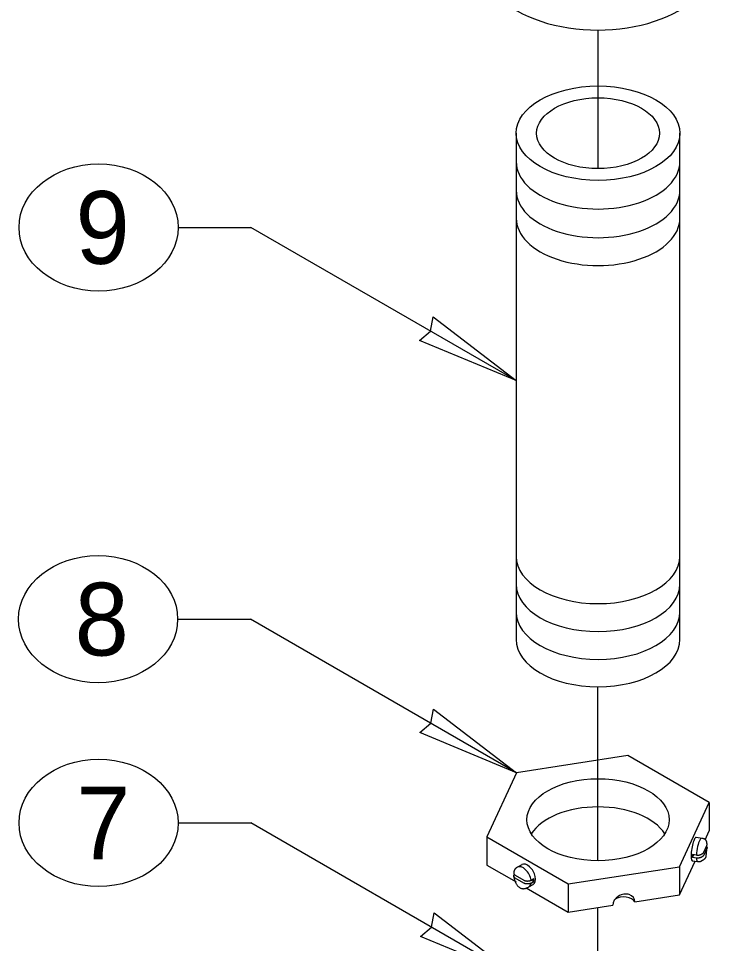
# Model space of a CAD drawing. Extents: x 99862 to 104211, y 98939 to 105076.
# Drawn here: x 100870.4 to 101022.8, y 101634.5 to 101838 of the extents above; entities that cross this region are included whole.
import ezdxf

# ---------------------------------------------------------------- set-up
doc = ezdxf.new("R2010")
doc.units = 0
for name, color, linetype in [('Level 15', 7, 'Continuous'), ('Level 2', 7, 'Continuous'), ('Level 20', 7, 'Continuous'), ('Level 8', 7, 'Continuous'), ('Level 9', 7, 'Continuous')]:
    doc.layers.add(name, color=color, linetype=linetype)

msp = doc.modelspace()

# ---------------------------------------------------------------- linework, layer by layer
at = {"layer": 'Level 15'}
for p, q in [((100997.88, 101804.98), (100997.88, 101835.47)), ((100905.56, 101792.04), (100921.56, 101792.04)), ((100979.88, 101758.37), (100921.56, 101792.04)), ((100905.44, 101705.87), (100921.44, 101705.87)), ((100979.98, 101672.07), (100921.44, 101705.87)), ((100997.83, 101652.72), (100997.83, 101691)), ((100905.56, 101661.03), (100921.56, 101661.03)), ((100980.1, 101627.23), (100921.56, 101661.03)), ((100997.83, 101608), (100997.83, 101642.43))]:
    msp.add_line(p, q, dxfattribs=at)
for points in [[(100979.88, 101758.37), (100958.62, 101767.2), (100961.03, 101769.26), (100961.61, 101772.37)], [(100979.98, 101672.07), (100958.72, 101680.9), (100961.12, 101682.96), (100961.7, 101686.07)], [(100980.1, 101627.23), (100958.84, 101636.06), (100961.24, 101638.12), (100961.82, 101641.23)]]:
    msp.add_lwpolyline(points, close=True, dxfattribs=at)
at = {"layer": 'Level 2'}
msp.add_ellipse((100997.83, 101849.9), major_axis=(-25, 0), ratio=0.57735, start_param=0, end_param=3.141593, dxfattribs=at)
at = {"layer": 'Level 20'}
for centre in [(100888.06, 101792.04), (100887.94, 101705.87), (100888.06, 101661.03)]:
    msp.add_ellipse(centre, major_axis=(-17.5, 0), ratio=0.8, dxfattribs=at)
at = {"layer": 'Level 8'}
for p, q in [((101004.43, 101675.85), (100979.98, 101672.07)), ((101022.33, 101665.52), (101004.43, 101675.85)), ((100979.98, 101672.07), (100973.43, 101657.95)), ((101015.78, 101651.4), (101022.33, 101665.52)), ((101022.33, 101665.52), (101022.33, 101659.32)), ((100973.43, 101657.95), (100973.43, 101651.75)), ((100973.43, 101657.95), (100991.33, 101647.62)), ((101020.77, 101657.63), (101019.43, 101657.83)), ((101021.4, 101657.31), (101022.33, 101659.32)), ((101021.12, 101654.58), (101021.81, 101656.05)), ((101021.81, 101655.4), (101021.12, 101653.92)), ((101019.51, 101653.97), (101018.66, 101654.1)), ((101018.66, 101653.45), (101018.94, 101654.05)), ((101019.51, 101653.31), (101018.66, 101653.45)), ((100973.43, 101651.75), (100979.84, 101648.05)), ((100981.13, 101651.85), (100980.15, 101651.29)), ((100991.33, 101647.62), (101015.78, 101651.4)), ((101015.78, 101645.2), (101019.22, 101652.63)), ((101015.78, 101651.4), (101015.78, 101645.2)), ((101018.59, 101652.73), (101019.76, 101652.55)), ((100979.67, 101649.53), (100981.54, 101648.45)), ((100981.54, 101647.8), (100979.67, 101648.88)), ((100982.65, 101646.96), (100983.63, 101647.52)), ((100983.15, 101648.44), (100983.77, 101648.8)), ((100983.15, 101647.79), (100983.77, 101648.15)), ((100983.2, 101648.48), (100983.77, 101648.15)), ((100991.33, 101647.62), (100991.33, 101641.42)), ((100982.08, 101646.76), (100991.33, 101641.42)), ((101005.97, 101643.68), (101015.78, 101645.2)), ((100991.33, 101641.42), (101001.14, 101642.94))]:
    msp.add_line(p, q, dxfattribs=at)
msp.add_ellipse((100997.88, 101661.74), major_axis=(15.63, 0), ratio=0.57735, dxfattribs=at)
for centre, major_axis, ratio, start_param, end_param in [((100997.88, 101655.54), (15.63, 0), 0.57735, 0.350805, 2.790788), ((101018.98, 101655.2), (-0.38, -2.47), 0.211325, 3.7149, 6.283185), ((101019.05, 101655.36), (0.38, 2.47), 0.211325, 6.283184, 6.973707), ((101020.23, 101655.18), (0.38, 2.47), 0.211325, 6.283184, 6.910448), ((101020.15, 101655.02), (0.38, 2.47), 0.211325, 0.497521, 2.04202), ((101020.23, 101655.18), (0.38, 2.47), 0.211325, 0.690521, 0.690521), ((101019.3, 101655.15), (0.38, 2.47), 0.211325, 2.04202, 2.363401), ((101020.15, 101655.02), (0.38, 2.47), 0.211325, 2.363401, 3.141593), ((100981.4, 101649.12), (1.25, -2.17), 0.57735, 0.946089, 3.141593), ((100982.38, 101649.69), (1.25, -2.17), 0.57735, 6.283185, 9.424778), ((100981.4, 101649.12), (1.25, -2.17), 0.57735, 0, 0.624708), ((100982.02, 101649.48), (1.25, -2.17), 0.57735, 0.624708, 0.946089), ((101003.55, 101643.31), (2.27, 1.05), 0.788675, 5.932306, 9.073899), ((101003.55, 101643.31), (2.5, 0), 0.57735, 0.261799, 2.46451)]:
    msp.add_ellipse(centre, major_axis=major_axis, ratio=ratio, start_param=start_param, end_param=end_param, dxfattribs=at)
for points, degree in [([(101021.85, 101656.26), (101021.85, 101656.78), (101021.49, 101657.52), (101020.77, 101657.63)], 2), ([(101020.75, 101652.78), (101021.61, 101653.15), (101021.71, 101654.39), (101021.85, 101655.55)], 2), ([(101021.73, 101655.87), (101021.78, 101655.82), (101021.81, 101655.76), (101021.83, 101655.7), (101021.85, 101655.62), (101021.85, 101655.55), (101021.84, 101655.48), (101021.83, 101655.45), (101021.82, 101655.42), (101021.81, 101655.4)], 3), ([(101021.81, 101656.05), (101021.82, 101656.08), (101021.84, 101656.12), (101021.84, 101656.15), (101021.85, 101656.19), (101021.85, 101656.23), (101021.85, 101656.26)], 3), ([(101019.51, 101653.97), (101019.58, 101653.96), (101019.65, 101653.95), (101019.72, 101653.95), (101019.84, 101653.94), (101019.97, 101653.95), (101020.09, 101653.97), (101020.21, 101653.99), (101020.32, 101654.02), (101020.42, 101654.06), (101020.53, 101654.1), (101020.62, 101654.15), (101020.69, 101654.21)], 3), ([(101020.69, 101653.56), (101020.62, 101653.5), (101020.52, 101653.44), (101020.41, 101653.4), (101020.3, 101653.36), (101020.18, 101653.33), (101020.06, 101653.31), (101019.94, 101653.29), (101019.81, 101653.29), (101019.69, 101653.29), (101019.63, 101653.3), (101019.57, 101653.3), (101019.51, 101653.31)], 3), ([(101020.69, 101654.21), (101020.79, 101654.25), (101020.87, 101654.3), (101020.93, 101654.35), (101021.01, 101654.41), (101021.07, 101654.47), (101021.11, 101654.54), (101021.11, 101654.56), (101021.12, 101654.57), (101021.12, 101654.58)], 3), ([(101021.12, 101653.92), (101021.12, 101653.92), (101021.12, 101653.92), (101021.12, 101653.92), (101021.08, 101653.84), (101021.02, 101653.76), (101020.94, 101653.7), (101020.87, 101653.64), (101020.79, 101653.6), (101020.69, 101653.56)], 3), ([(100980.15, 101651.29), (100979.7, 101651.03), (100979.42, 101650.56), (100979.34, 101650.07)], 2), ([(101019.76, 101652.55), (101020.19, 101652.51), (101020.51, 101652.6), (101020.75, 101652.78)], 2), ([(100979.34, 101650.07), (100979.33, 101650.03), (100979.33, 101649.99), (100979.33, 101649.95), (100979.34, 101649.88), (100979.38, 101649.81), (100979.43, 101649.74), (100979.48, 101649.68), (100979.55, 101649.61), (100979.63, 101649.56), (100979.65, 101649.55), (100979.66, 101649.54), (100979.67, 101649.53)], 3), ([(100979.34, 101650.07), (100979.33, 101650.03), (100979.33, 101649.99), (100979.33, 101649.95), (100979.34, 101649.88), (100979.38, 101649.81), (100979.43, 101649.74), (100979.48, 101649.68), (100979.55, 101649.61), (100979.63, 101649.56), (100979.65, 101649.55), (100979.66, 101649.54), (100979.67, 101649.53)], 3), ([(100979.67, 101648.88), (100979.67, 101648.88), (100979.67, 101648.88), (100979.67, 101648.88), (100979.57, 101648.94), (100979.49, 101649.01), (100979.43, 101649.09), (100979.37, 101649.16), (100979.34, 101649.23), (100979.33, 101649.31), (100979.33, 101649.38), (100979.34, 101649.46), (100979.37, 101649.53), (100979.4, 101649.58), (100979.44, 101649.63), (100979.48, 101649.68)], 3), ([(100979.67, 101648.88), (100979.67, 101648.88), (100979.67, 101648.88), (100979.67, 101648.88), (100979.57, 101648.94), (100979.49, 101649.01), (100979.43, 101649.09), (100979.37, 101649.16), (100979.34, 101649.23), (100979.33, 101649.31), (100979.33, 101649.38), (100979.34, 101649.46), (100979.37, 101649.53), (100979.4, 101649.58), (100979.44, 101649.63), (100979.48, 101649.68)], 3), ([(100979.34, 101649.29), (100979.58, 101647.74), (100981.3, 101646.17), (100982.65, 101646.96)], 2), ([(100979.34, 101649.29), (100979.58, 101647.74), (100981.3, 101646.17), (100982.65, 101646.96)], 2), ([(100981.54, 101648.45), (100981.59, 101648.43), (100981.63, 101648.41), (100981.68, 101648.39), (100981.79, 101648.34), (100981.92, 101648.3), (100982.05, 101648.28), (100982.17, 101648.26), (100982.31, 101648.25), (100982.44, 101648.26), (100982.56, 101648.26), (100982.69, 101648.28), (100982.81, 101648.31), (100982.92, 101648.34), (100983.03, 101648.38), (100983.12, 101648.43), (100983.13, 101648.43), (100983.14, 101648.44), (100983.15, 101648.44)], 3), ([(100981.54, 101648.45), (100981.59, 101648.43), (100981.63, 101648.41), (100981.68, 101648.39), (100981.79, 101648.34), (100981.92, 101648.3), (100982.05, 101648.28), (100982.17, 101648.26), (100982.31, 101648.25), (100982.44, 101648.26), (100982.56, 101648.26), (100982.69, 101648.28), (100982.81, 101648.31), (100982.92, 101648.34), (100983.03, 101648.38), (100983.12, 101648.43), (100983.13, 101648.43), (100983.14, 101648.44), (100983.15, 101648.44)], 3), ([(100983.15, 101647.79), (100983.11, 101647.77), (100983.08, 101647.75), (100983.04, 101647.74), (100982.95, 101647.69), (100982.83, 101647.66), (100982.72, 101647.64), (100982.6, 101647.61), (100982.47, 101647.6), (100982.35, 101647.6), (100982.22, 101647.6), (100982.1, 101647.62), (100981.98, 101647.64), (100981.86, 101647.66), (100981.75, 101647.7), (100981.65, 101647.75), (100981.61, 101647.76), (100981.58, 101647.78), (100981.54, 101647.8)], 3), ([(100983.15, 101647.79), (100983.11, 101647.77), (100983.08, 101647.75), (100983.04, 101647.74), (100982.95, 101647.69), (100982.83, 101647.66), (100982.72, 101647.64), (100982.6, 101647.61), (100982.47, 101647.6), (100982.35, 101647.6), (100982.22, 101647.6), (100982.1, 101647.62), (100981.98, 101647.64), (100981.86, 101647.66), (100981.75, 101647.7), (100981.65, 101647.75), (100981.61, 101647.76), (100981.58, 101647.78), (100981.54, 101647.8)], 3)]:
    msp.add_open_spline(points, degree=degree, dxfattribs=at)
at = {"layer": 'Level 9'}
for p, q in [((100979.88, 101812.78), (100979.88, 101701.39)), ((101015.88, 101701.39), (101015.88, 101812.78))]:
    msp.add_line(p, q, dxfattribs=at)
for major_axis in [(18, 0), (13.5, 0)]:
    msp.add_ellipse((100997.88, 101812.78), major_axis=major_axis, ratio=0.57735, dxfattribs=at)
for centre, start_param in [((100997.88, 101806.49), 3.141588), ((100997.88, 101800.18), 3.141587), ((100997.88, 101794.05), 3.141585), ((100997.88, 101719.67), 3.141593), ((100997.88, 101713.54), 3.141593), ((100997.88, 101707.41), 3.141593), ((100997.88, 101701.39), 3.141593)]:
    msp.add_ellipse(centre, major_axis=(18, 0), ratio=0.57735, start_param=start_param, end_param=6.283185, dxfattribs=at)

# ---------------------------------------------------------------- texts
at = {"layer": 'Level 20'}
for s, p in [('9', (100882.99, 101784.04)), ('8', (100882.79, 101697.87)), ('7', (100883.14, 101653.03))]:
    msp.add_text(s, height=16, rotation=360, dxfattribs=at).set_placement(p)

doc.saveas('drawing.dxf')
